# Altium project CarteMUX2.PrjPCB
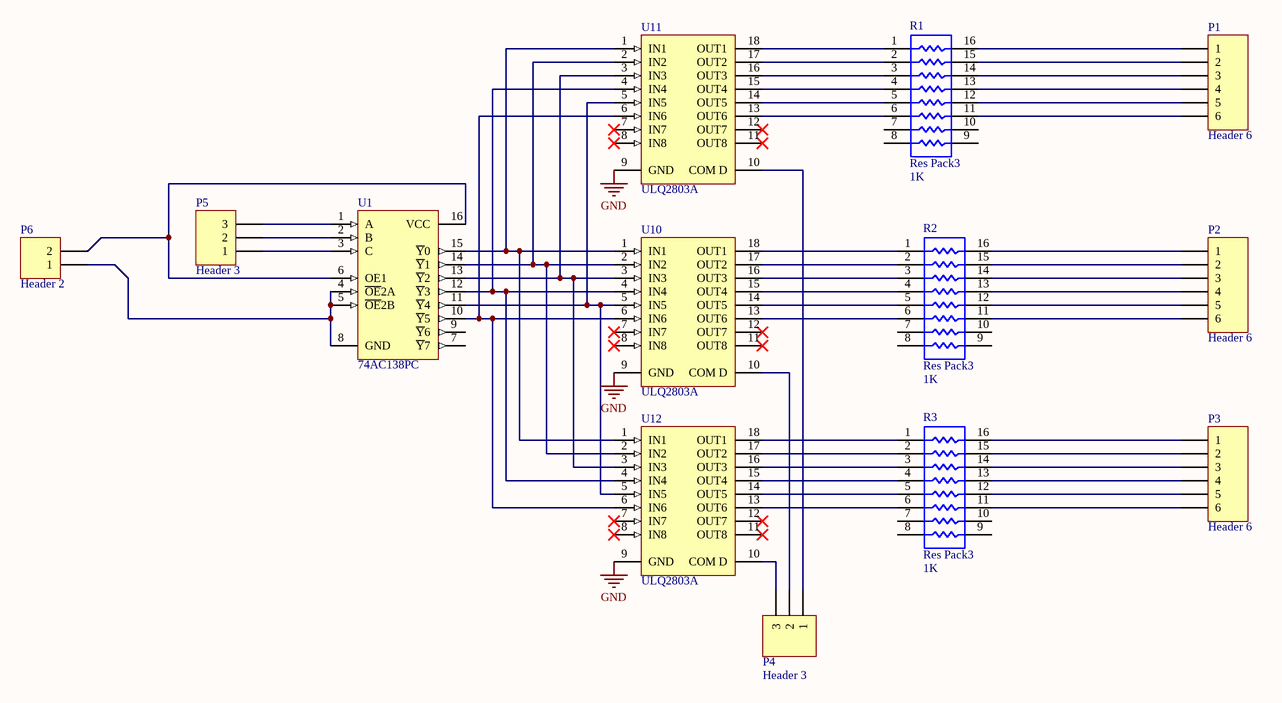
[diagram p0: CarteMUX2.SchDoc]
1 sheet, 13 parts. Net scope: global (net labels, ports and power ports of the same name join across sheets).
Board file: CarteMUX2.PcbDoc

## Sheet CarteMUX2.SchDoc
size A4

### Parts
P1  Header 6  [HDR1X6]
P2  Header 6  [HDR1X6]
P3  Header 6  [HDR1X6]
P4  Header 3  [HDR1X3]
P5  Header 3  [HDR1X3]
P6  Header 2  [HDR1X2]
R1  Res Pack3  value 1K  [SO-16_N]
R2  Res Pack3  value 1K  [SO-16_N]
R3  Res Pack3  value 1K  [SO-16_N]
U1  74AC138PC  [N16E]
U10  ULQ2803A  [DIP18]
U11  ULQ2803A  [DIP18]
U12  ULQ2803A  [DIP18]

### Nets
GND: U10.9(GND) U11.9(GND) U12.9(GND)
NetP1_1: P1.1 R1.16
NetP1_2: P1.2 R1.15
NetP1_3: P1.3 R1.14
NetP1_4: P1.4 R1.13
NetP1_5: P1.5 R1.12
NetP1_6: P1.6 R1.11
NetP2_1: P2.1 R2.16
NetP2_2: P2.2 R2.15
NetP2_3: P2.3 R2.14
NetP2_4: P2.4 R2.13
NetP2_5: P2.5 R2.12
NetP2_6: P2.6 R2.11
NetP3_1: P3.1 R3.16
NetP3_2: P3.2 R3.15
NetP3_3: P3.3 R3.14
NetP3_4: P3.4 R3.13
NetP3_5: P3.5 R3.12
NetP3_6: P3.6 R3.11
NetP4_1: P4.1 U11.10(COM_D)
NetP4_2: P4.2 U10.10(COM_D)
NetP4_3: P4.3 U12.10(COM_D)
NetP5_1: P5.1 U1.3(C)
NetP5_2: P5.2 U1.2(B)
NetP5_3: P5.3 U1.1(A)
NetP6_1: P6.1 U1.4(~{OE}2A) U1.5(~{OE}2B) U1.8(GND)
NetP6_2: P6.2 U1.6(OE1) U1.16(VCC)
NetR1_1: R1.1 U11.18(OUT1)
NetR1_2: R1.2 U11.17(OUT2)
NetR1_3: R1.3 U11.16(OUT3)
NetR1_4: R1.4 U11.15(OUT4)
NetR1_5: R1.5 U11.14(OUT5)
NetR1_6: R1.6 U11.13(OUT6)
NetR2_1: R2.1 U10.18(OUT1)
NetR2_2: R2.2 U10.17(OUT2)
NetR2_3: R2.3 U10.16(OUT3)
NetR2_4: R2.4 U10.15(OUT4)
NetR2_5: R2.5 U10.14(OUT5)
NetR2_6: R2.6 U10.13(OUT6)
NetR3_1: R3.1 U12.18(OUT1)
NetR3_2: R3.2 U12.17(OUT2)
NetR3_3: R3.3 U12.16(OUT3)
NetR3_4: R3.4 U12.15(OUT4)
NetR3_5: R3.5 U12.14(OUT5)
NetR3_6: R3.6 U12.13(OUT6)
NetU1_10: U1.10(~{Y}5) U10.6(IN6) U11.6(IN6) U12.6(IN6)
NetU1_11: U1.11(~{Y}4) U10.5(IN5) U11.5(IN5) U12.5(IN5)
NetU1_12: U1.12(~{Y}3) U10.4(IN4) U11.4(IN4) U12.4(IN4)
NetU1_13: U1.13(~{Y}2) U10.3(IN3) U11.3(IN3) U12.3(IN3)
NetU1_14: U1.14(~{Y}1) U10.2(IN2) U11.2(IN2) U12.2(IN2)
NetU1_15: U1.15(~{Y}0) U10.1(IN1) U11.1(IN1) U12.1(IN1)

Not connected (* = marked no-connect by the designer): R1 7 8 9 10; R2 7 8 9 10; R3 7 8 9 10; U1 7(~{Y}7) 9(~{Y}6); U10 7(IN7)* 8(IN8)* 11(OUT8)* 12(OUT7)*; U11 7(IN7)* 8(IN8)* 11(OUT8)* 12(OUT7)*; U12 7(IN7)* 8(IN8)* 11(OUT8)* 12(OUT7)*

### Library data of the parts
P1-P3 = Header 6: Header, 6-Pin
P4 P5 = Header 3: Header, 3-Pin
P6 = Header 2: Header, 2-Pin
R1-R3 = Res Pack3: Isolated Resistor Network
U1 = 74AC138PC: 1-of-8 Decoder/Multiplexer
U10-U12 = ULQ2803A: Eight Darlington Array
